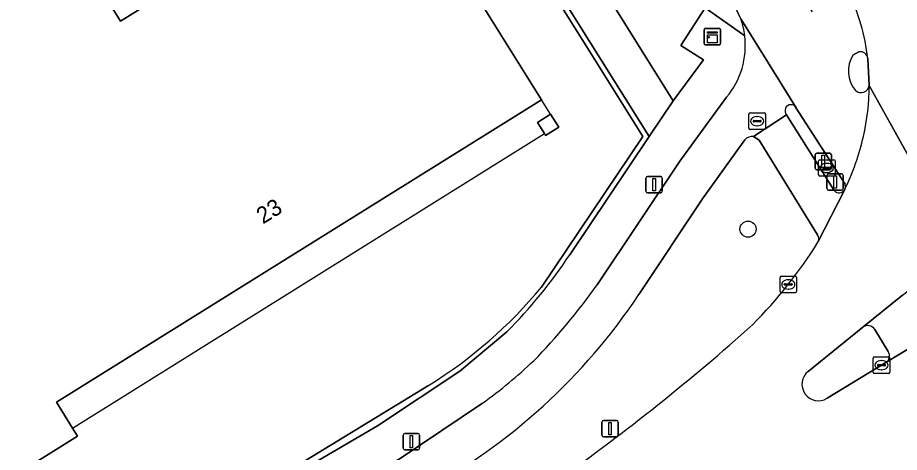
# Model space of a CAD drawing. Extents: x 156702 to 158052, y 387630 to 388992.
# Drawn here: x 157910.9 to 157964.3, y 388566 to 388592.3 of the extents above; entities that cross this region are included whole.
import ezdxf

# ---------------------------------------------------------------- set-up
doc = ezdxf.new("R2010")
doc.units = 0
for name, color, linetype in [('IMGEO_Berm_groen', 7, 'Continuous'), ('IMGEO_Boom', 7, 'Continuous'), ('IMGEO_Brandkraan', 7, 'Continuous'), ('IMGEO_Drukknoppaal', 7, 'Continuous'), ('IMGEO_Erf', 7, 'Continuous'), ('IMGEO_Fietspad_open', 7, 'Continuous'), ('IMGEO_Groenvoorziening', 7, 'Continuous'), ('IMGEO_Hek', 7, 'Continuous'), ('IMGEO_Kast', 7, 'Continuous'), ('IMGEO_Kolk', 7, 'Continuous'), ('IMGEO_Lichtmast', 7, 'Continuous'), ('IMGEO_Pand', 7, 'Continuous'), ('IMGEO_Pand_nummerreeks', 7, 'Continuous'), ('IMGEO_Pand_overbouw', 7, 'Continuous'), ('IMGEO_Rijbaan_lokaal_gesloten', 7, 'Continuous'), ('IMGEO_Rijbaan_regionaal_gesloten', 7, 'Continuous'), ('IMGEO_Rioolput', 7, 'Continuous'), ('IMGEO_Verkeerseiland_gesloten', 7, 'Continuous'), ('IMGEO_Verkeerseiland_open', 7, 'Continuous'), ('IMGEO_Verkeersregelinstallatiepaal', 7, 'Continuous'), ('IMGEO_Voetpad_open', 7, 'Continuous')]:
    doc.layers.add(name, color=color, linetype=linetype)

msp = doc.modelspace()

# ---------------------------------------------------------------- linework, layer by layer
at = {"layer": 'IMGEO_Berm_groen'}
for points in [[(157954.927, 388584.899), (157952.413, 388581.397), (157948.511, 388575.538)], [(157959.34, 388579.16), (157955.792, 388584.884), (157955.46, 388585.106)]]:
    msp.add_lwpolyline(points, dxfattribs=at)
for centre, radius, start, end in [((157955.356, 388584.584), 0.532, 78.7412, 143.7079), ((157958.922, 388578.915), 0.485, 334.4499, 30.3429), ((157934.754, 388594.145), 29.047, 315.3164, 327.8927), ((157918.015, 388595.904), 36.671, 298.3632, 326.264), ((157866.867, 388672.709), 132.809, 305.31667, 311.81023)]:
    msp.add_arc(centre, radius, start, end, dxfattribs=at)
at = {"layer": 'IMGEO_Boom'}
msp.add_circle((157955.124, 388579.503), 0.489, dxfattribs=at)
at = {"layer": 'IMGEO_Brandkraan'}
for p, q in [((157959.401, 388582.78), (157959.401, 388583.632)), ((157959.476, 388583.706), (157960.328, 388583.706)), ((157959.703, 388583.249), (157960.101, 388583.249)), ((157959.889, 388583.486), (157959.914, 388583.486)), ((157960.402, 388583.632), (157960.402, 388582.78)), ((157960.328, 388582.706), (157959.476, 388582.706)), ((157959.66, 388583.2), (157959.66, 388583.212)), ((157960.098, 388583.163), (157959.7, 388583.163)), ((157959.912, 388582.926), (157959.887, 388582.926)), ((157960.144, 388583.212), (157960.144, 388583.2))]:
    msp.add_line(p, q, dxfattribs=at)
for points in [[(157959.401, 388582.78), (157959.401, 388583.632)], [(157959.476, 388583.706), (157960.328, 388583.706)], [(157960.402, 388583.632), (157960.402, 388582.78)], [(157960.328, 388582.706), (157959.476, 388582.706)]]:
    msp.add_lwpolyline(points, dxfattribs=at)
for centre, radius, start, end in [((157959.478, 388583.63), 0.0765, 91.552, 178.448), ((157959.478, 388583.63), 0.0765, 91.552, 178.448), ((157959.7, 388583.209), 0.0403, 85.8775, 175.7526), ((157960.105, 388583.211), 0.0386, 1.7309, 96.639), ((157960.326, 388583.63), 0.0765, 1.552, 88.448), ((157960.326, 388583.63), 0.0765, 1.552, 88.448), ((157959.478, 388582.782), 0.0765, 181.552, 268.448), ((157959.478, 388582.782), 0.0765, 181.552, 268.448), ((157959.697, 388583.199), 0.0366, 178.938, 274.7102), ((157960.101, 388583.206), 0.043, 264.8664, 352.4533), ((157960.326, 388582.782), 0.0765, 271.552, 358.448), ((157960.326, 388582.782), 0.0765, 271.552, 358.448)]:
    msp.add_arc(centre, radius, start, end, dxfattribs=at)
for centre, major_axis, ratio, start_param, end_param in [((157959.888, 388583.206), (-0.387, 0.002), 0.722429, 4.712389, 7.853982), ((157959.913, 388583.206), (-0.39, 0.002), 0.717154, 1.570796, 4.712389)]:
    msp.add_ellipse(centre, major_axis=major_axis, ratio=ratio, start_param=start_param, end_param=end_param, dxfattribs=at)
at = {"layer": 'IMGEO_Drukknoppaal'}
for p, q in [((157959.183, 388583.196), (157959.183, 388583.996)), ((157959.183, 388583.996), (157959.183, 388583.196)), ((157959.283, 388584.096), (157960.073, 388584.096)), ((157960.073, 388584.096), (157959.283, 388584.096)), ((157960.173, 388583.996), (157960.173, 388583.196)), ((157960.173, 388583.196), (157960.173, 388583.996)), ((157960.073, 388583.096), (157959.283, 388583.096)), ((157959.283, 388583.096), (157960.073, 388583.096))]:
    msp.add_line(p, q, dxfattribs=at)
msp.add_lwpolyline([(157959.603, 388583.971), (157959.753, 388583.971), (157959.753, 388583.221), (157959.603, 388583.221), (157959.603, 388583.971)], dxfattribs=at)
for centre, start, end in [((157959.283, 388583.996), 90, 180), ((157959.283, 388583.996), 90, 180), ((157960.073, 388583.996), 0, 90), ((157960.073, 388583.996), 360, 90), ((157959.283, 388583.196), 180, 270), ((157959.283, 388583.196), 180, 270), ((157960.073, 388583.196), 270, 0), ((157960.073, 388583.196), 270, 0)]:
    msp.add_arc(centre, 0.1, start, end, dxfattribs=at)
at = {"layer": 'IMGEO_Erf'}
for points in [[(157948.757, 388585.103), (157945.61, 388590.115), (157919.697, 388631.383)], [(157863.84, 388596.769), (157846.071, 388585.831), (157845.161, 388585.276), (157845.206, 388585.216), (157845.979, 388584.198), (157852.72, 388575.415), (157852.82, 388575.493), (157856.311, 388570.878), (157873.067, 388548.722), (157876.307, 388544.438), (157879.966, 388539.6), (157881.966, 388538.145), (157884.382, 388537.75), (157886.516, 388538.265), (157912.593, 388554.443), (157921.94, 388561.605), (157926.695, 388564.507), (157935.759, 388570.044)], [(157942.609, 388575.997), (157948.757, 388585.103)]]:
    msp.add_lwpolyline(points, dxfattribs=at)
for points in [[(157913.225, 388569.027), (157914.19, 388567.452), (157914.494, 388566.97), (157908.34, 388563.13), (157908.075, 388563.555), (157891.158, 388552.943), (157865.87, 388592.617), (157883.193, 388603.423), (157883.007, 388603.739), (157889.176, 388607.593), (157889.39, 388607.278), (157898.345, 388612.873), (157902.499, 388615.468), (157917.093, 388592.095), (157924.551, 388596.738), (157933.319, 388602.195), (157942.615, 388587.321)], [(157942.786, 388585.292), (157942.362, 388585.956), (157943.147, 388586.459), (157943.658, 388585.673), (157942.858, 388585.18)]]:
    msp.add_lwpolyline(points, close=True, dxfattribs=at)
msp.add_arc((157921.347, 388593.545), 27.568, 301.5184, 320.4662, dxfattribs=at)
at = {"layer": 'IMGEO_Fietspad_open'}
for points in [[(157959.029, 388592.654), (157957.588, 388594.939), (157954.357, 388592.926), (157954.548, 388592.518), (157954.685, 388592.236), (157956.324, 388589.617), (157958.047, 388586.855), (157958.045, 388586.83), (157960.999, 388582.223)], [(157958.045, 388586.83), (157958.047, 388586.855), (157956.324, 388589.617), (157954.685, 388592.236)], [(157961.476, 388590.034), (157961.842, 388590.238)], [(157953.825, 388587.483), (157950.99, 388583.61), (157945.972, 388576.134)], [(157955.46, 388585.106), (157957.459, 388586.428)], [(157948.511, 388575.538), (157952.413, 388581.397), (157954.927, 388584.899)], [(157939.034, 388568.961), (157934.042, 388565.621), (157923.682, 388559.554)]]:
    msp.add_lwpolyline(points, dxfattribs=at)
for centre, radius, start, end in [((157949.872, 388588.389), 12.592, 6.6249, 25.8715), ((157950.055, 388590.624), 4.902, 6.9137, 19.1984), ((157950.053, 388590.619), 4.905, 320.2617, 6.9692), ((157961.907, 388589.762), 0.48, 9.569, 97.7205), ((157962.998, 388589.073), 1.8, 147.74, 220.6754), ((157961.97, 388588.275), 0.504, 228.0298, 351.3299), ((157948.084, 388588.291), 14.386, 347.2395, 359.6319), ((157957.72, 388586.676), 0.36, 25.2943, 223.6064), ((157955.356, 388584.584), 0.532, 78.7412, 143.7079), ((157947.944, 388588.313), 14.527, 333.8086, 347.2797), ((157960.586, 388582.087), 0.434, 334.6452, 18.2464), ((157915.537, 388597.592), 37.239, 315.5843, 324.8144), ((157918.015, 388595.904), 36.671, 298.3632, 326.264), ((157921.547, 388593.233), 29.915, 305.7707, 313.4907)]:
    msp.add_arc(centre, radius, start, end, dxfattribs=at)
at = {"layer": 'IMGEO_Groenvoorziening'}
for points in [[(157954.685, 388592.236), (157954.548, 388592.518), (157954.357, 388592.926), (157954.322, 388592.982), (157844.53, 388769.241)], [(157880.239, 388699.921), (157928.508, 388622.637), (157945.606, 388595.262), (157950.595, 388587.277), (157952.433, 388589.75), (157951.047, 388590.629), (157952.528, 388592.898), (157954.922, 388591.214)], [(157944.325, 388577.946), (157949.123, 388585.105), (157943.354, 388594.324), (157926.051, 388621.896), (157924.743, 388623.999), (157911.853, 388644.72), (157899.219, 388665.03), (157885.512, 388656.483), (157868.846, 388646.09), (157821.438, 388616.579), (157821.49, 388616.464), (157825.955, 388610.584), (157827.357, 388611.329), (157826.47, 388612.778), (157823.972, 388616.855), (157851.434, 388634.015), (157854.036, 388629.957), (157854.857, 388628.676), (157863.382, 388633.842), (157862.483, 388635.263), (157859.899, 388639.35)], [(157859.899, 388639.35), (157891.839, 388659.234), (157894.466, 388655.043), (157898.194, 388657.38), (157908.656, 388640.687), (157904.927, 388638.35), (157911.548, 388627.786), (157906.588, 388624.86), (157907.31, 388623.673), (157919.697, 388631.383), (157945.61, 388590.115), (157948.757, 388585.103), (157942.609, 388575.997)], [(157935.759, 388570.044), (157926.695, 388564.507), (157921.94, 388561.605), (157912.593, 388554.443), (157886.516, 388538.265), (157884.382, 388537.75), (157881.966, 388538.145), (157879.966, 388539.6), (157876.307, 388544.438), (157876.167, 388544.326), (157879.78, 388539.386), (157881.963, 388537.803), (157884.345, 388537.434), (157886.442, 388537.927), (157914.286, 388554.915), (157915.878, 388556.27), (157918.49, 388558.725), (157922.488, 388561.637), (157932.675, 388567.591), (157937.655, 388570.903), (157940.514, 388573.276)]]:
    msp.add_lwpolyline(points, dxfattribs=at)
for centre, radius, start, end in [((157950.055, 388590.624), 4.902, 6.9137, 19.1984), ((157917.286, 388596.121), 32.579, 315.4756, 326.0914), ((157921.347, 388593.545), 27.568, 301.5184, 320.4662)]:
    msp.add_arc(centre, radius, start, end, dxfattribs=at)
at = {"layer": 'IMGEO_Hek'}
for points in [[(157907.31, 388623.673), (157919.697, 388631.383), (157945.61, 388590.115)], [(157945.61, 388590.115), (157948.757, 388585.103), (157942.609, 388575.997)], [(157935.759, 388570.044), (157926.695, 388564.507)]]:
    msp.add_lwpolyline(points, dxfattribs=at)
msp.add_arc((157921.347, 388593.545), 27.568, 301.5184, 320.4662, dxfattribs=at)
at = {"layer": 'IMGEO_Kast'}
for p, q in [((157952.462, 388590.731), (157952.462, 388591.572)), ((157952.462, 388591.572), (157952.462, 388590.731)), ((157952.537, 388591.656), (157953.378, 388591.656)), ((157953.378, 388591.656), (157952.537, 388591.656)), ((157953.462, 388591.581), (157953.462, 388590.74)), ((157953.462, 388590.74), (157953.462, 388591.581)), ((157953.387, 388590.656), (157952.546, 388590.656)), ((157952.546, 388590.656), (157953.387, 388590.656))]:
    msp.add_line(p, q, dxfattribs=at)
for points in [[(157952.657, 388591.446), (157953.257, 388591.446), (157953.257, 388591.361), (157952.657, 388591.361), (157952.657, 388591.446)], [(157952.657, 388591.271), (157953.257, 388591.271), (157953.257, 388590.782), (157952.657, 388590.782), (157952.657, 388591.271)]]:
    msp.add_lwpolyline(points, dxfattribs=at)
msp.add_circle((157952.741, 388591.12), 0.0377, dxfattribs=at)
for centre, start, end in [((157952.54, 388591.578), 92.4484, 184.2845), ((157952.54, 388591.578), 92.4484, 184.2845), ((157953.384, 388591.578), 2.4484, 94.2845), ((157953.384, 388591.578), 2.4484, 94.2845), ((157952.54, 388590.734), 182.4484, 274.2845), ((157952.54, 388590.734), 182.4484, 274.2845), ((157953.384, 388590.734), 272.4484, 4.2845), ((157953.384, 388590.734), 272.4484, 4.2845)]:
    msp.add_arc(centre, 0.0779, start, end, dxfattribs=at)
at = {"layer": 'IMGEO_Kolk'}
for p, q in [((157955.173, 388585.614), (157955.173, 388586.466)), ((157955.248, 388586.54), (157956.1, 388586.54)), ((157956.174, 388586.466), (157956.174, 388585.614)), ((157955.432, 388586.034), (157955.432, 388586.046)), ((157955.87, 388585.997), (157955.472, 388585.997)), ((157955.475, 388586.083), (157955.873, 388586.083)), ((157955.661, 388586.32), (157955.686, 388586.32)), ((157955.916, 388586.046), (157955.916, 388586.034)), ((157956.1, 388585.54), (157955.248, 388585.54)), ((157955.684, 388585.76), (157955.659, 388585.76)), ((157957.062, 388575.729), (157957.062, 388576.581)), ((157957.137, 388576.655), (157957.989, 388576.655)), ((157957.55, 388576.435), (157957.575, 388576.435)), ((157958.063, 388576.581), (157958.063, 388575.729)), ((157957.321, 388576.149), (157957.321, 388576.161)), ((157957.759, 388576.112), (157957.361, 388576.112)), ((157957.364, 388576.198), (157957.762, 388576.198)), ((157957.573, 388575.875), (157957.548, 388575.875)), ((157957.805, 388576.161), (157957.805, 388576.149)), ((157957.989, 388575.655), (157957.137, 388575.655))]:
    msp.add_line(p, q, dxfattribs=at)
for points in [[(157955.173, 388585.614), (157955.173, 388586.466)], [(157955.248, 388586.54), (157956.1, 388586.54)], [(157956.174, 388586.466), (157956.174, 388585.614)], [(157956.1, 388585.54), (157955.248, 388585.54)], [(157957.062, 388575.729), (157957.062, 388576.581)], [(157957.137, 388576.655), (157957.989, 388576.655)], [(157958.063, 388576.581), (157958.063, 388575.729)], [(157957.989, 388575.655), (157957.137, 388575.655)]]:
    msp.add_lwpolyline(points, dxfattribs=at)
for centre, radius, start, end in [((157955.25, 388586.464), 0.0765, 91.552, 178.448), ((157955.25, 388586.464), 0.0765, 91.552, 178.448), ((157956.098, 388586.464), 0.0765, 1.552, 88.448), ((157956.098, 388586.464), 0.0765, 1.552, 88.448), ((157955.472, 388586.043), 0.0403, 85.8775, 175.7526), ((157955.469, 388586.033), 0.0366, 178.938, 274.7102), ((157955.873, 388586.04), 0.043, 264.8664, 352.4533), ((157955.877, 388586.045), 0.0386, 1.7309, 96.639), ((157955.25, 388585.616), 0.0765, 181.552, 268.448), ((157955.25, 388585.616), 0.0765, 181.552, 268.448), ((157956.098, 388585.616), 0.0765, 271.552, 358.448), ((157956.098, 388585.616), 0.0765, 271.552, 358.448), ((157957.139, 388576.579), 0.0765, 91.552, 178.448), ((157957.139, 388576.579), 0.0765, 91.552, 178.448), ((157957.987, 388576.579), 0.0765, 1.552, 88.448), ((157957.987, 388576.579), 0.0765, 1.552, 88.448), ((157957.361, 388576.158), 0.0403, 85.8775, 175.7526), ((157957.358, 388576.148), 0.0366, 178.938, 274.7102), ((157957.762, 388576.155), 0.043, 264.8664, 352.4533), ((157957.766, 388576.16), 0.0386, 1.7309, 96.639), ((157957.139, 388575.731), 0.0765, 181.552, 268.448), ((157957.139, 388575.731), 0.0765, 181.552, 268.448), ((157957.987, 388575.731), 0.0765, 271.552, 358.448), ((157957.987, 388575.731), 0.0765, 271.552, 358.448)]:
    msp.add_arc(centre, radius, start, end, dxfattribs=at)
for centre, major_axis, ratio, start_param, end_param in [((157955.66, 388586.04), (-0.387, 0.002), 0.722429, 4.712389, 7.853982), ((157955.685, 388586.04), (-0.39, 0.002), 0.717154, 1.570796, 4.712389), ((157957.549, 388576.155), (-0.387, 0.002), 0.722429, 4.712389, 7.853982), ((157957.574, 388576.155), (-0.39, 0.002), 0.717154, 1.570796, 4.712389)]:
    msp.add_ellipse(centre, major_axis=major_axis, ratio=ratio, start_param=start_param, end_param=end_param, dxfattribs=at)
at = {"layer": 'IMGEO_Lichtmast'}
for p, q in [((157949.039, 388582.697), (157949.829, 388582.697)), ((157949.829, 388582.697), (157949.039, 388582.697)), ((157948.939, 388581.797), (157948.939, 388582.597)), ((157948.939, 388582.597), (157948.939, 388581.797)), ((157949.929, 388582.597), (157949.929, 388581.797)), ((157949.929, 388581.797), (157949.929, 388582.597)), ((157949.829, 388581.697), (157949.039, 388581.697)), ((157949.039, 388581.697), (157949.829, 388581.697)), ((157946.268, 388567.025), (157946.268, 388567.825)), ((157946.268, 388567.825), (157946.268, 388567.025)), ((157946.368, 388567.925), (157947.158, 388567.925)), ((157947.158, 388567.925), (157946.368, 388567.925)), ((157947.258, 388567.825), (157947.258, 388567.025)), ((157947.258, 388567.025), (157947.258, 388567.825)), ((157934.231, 388566.235), (157934.231, 388567.035)), ((157934.231, 388567.035), (157934.231, 388566.235)), ((157934.331, 388567.135), (157935.121, 388567.135)), ((157935.121, 388567.135), (157934.331, 388567.135)), ((157935.221, 388567.035), (157935.221, 388566.235)), ((157935.221, 388566.235), (157935.221, 388567.035)), ((157947.158, 388566.925), (157946.368, 388566.925)), ((157946.368, 388566.925), (157947.158, 388566.925)), ((157935.121, 388566.135), (157934.331, 388566.135)), ((157934.331, 388566.135), (157935.121, 388566.135))]:
    msp.add_line(p, q, dxfattribs=at)
for points in [[(157949.359, 388582.572), (157949.509, 388582.572), (157949.509, 388581.822), (157949.359, 388581.822), (157949.359, 388582.572)], [(157946.688, 388567.8), (157946.838, 388567.8), (157946.838, 388567.05), (157946.688, 388567.05), (157946.688, 388567.8)], [(157934.651, 388567.01), (157934.801, 388567.01), (157934.801, 388566.26), (157934.651, 388566.26), (157934.651, 388567.01)]]:
    msp.add_lwpolyline(points, dxfattribs=at)
for centre, start, end in [((157949.039, 388582.597), 90, 180), ((157949.039, 388582.597), 90, 180), ((157949.829, 388582.597), 0, 90), ((157949.829, 388582.597), 360, 90), ((157949.039, 388581.797), 180, 270), ((157949.039, 388581.797), 180, 270), ((157949.829, 388581.797), 270, 0), ((157949.829, 388581.797), 270, 0), ((157946.368, 388567.825), 90, 180), ((157946.368, 388567.825), 90, 180), ((157947.158, 388567.825), 0, 90), ((157947.158, 388567.825), 360, 90), ((157934.331, 388567.035), 90, 180), ((157934.331, 388567.035), 90, 180), ((157935.121, 388567.035), 0, 90), ((157935.121, 388567.035), 360, 90), ((157946.368, 388567.025), 180, 270), ((157946.368, 388567.025), 180, 270), ((157947.158, 388567.025), 270, 0), ((157947.158, 388567.025), 270, 0), ((157934.331, 388566.235), 180, 270), ((157934.331, 388566.235), 180, 270), ((157935.121, 388566.235), 270, 0), ((157935.121, 388566.235), 270, 0)]:
    msp.add_arc(centre, 0.1, start, end, dxfattribs=at)
at = {"layer": 'IMGEO_Pand'}
for points in [[(157914.19, 388567.452), (157913.225, 388569.027), (157942.615, 388587.321), (157933.319, 388602.195), (157924.551, 388596.738), (157917.093, 388592.095), (157902.499, 388615.468), (157898.345, 388612.873), (157889.39, 388607.278), (157889.176, 388607.593), (157883.007, 388603.739), (157883.193, 388603.423), (157865.87, 388592.617), (157891.158, 388552.943), (157908.075, 388563.555), (157908.34, 388563.13), (157914.494, 388566.97)], [(157942.858, 388585.18), (157943.658, 388585.673), (157943.147, 388586.459), (157942.362, 388585.956), (157942.786, 388585.292)]]:
    msp.add_lwpolyline(points, close=True, dxfattribs=at)
at = {"layer": 'IMGEO_Pand_overbouw'}
msp.add_lwpolyline([(157943.658, 388585.673), (157943.147, 388586.459), (157942.615, 388587.321), (157913.225, 388569.027), (157914.19, 388567.452), (157942.786, 388585.292), (157942.858, 388585.18)], close=True, dxfattribs=at)
at = {"layer": 'IMGEO_Rijbaan_lokaal_gesloten'}
for points in [[(157958.762, 388570.89), (157962.072, 388573.558), (157964.476, 388575.497), (157964.547, 388575.554), (157967.86, 388578.249), (157967.966, 388578.311), (157962.469, 388588.199)], [(157960.979, 388581.901), (157959.359, 388578.706)], [(157975.665, 388567.04), (157969.867, 388575.31), (157969.735, 388575.217), (157966.125, 388573.037), (157966.08, 388573.009), (157963.461, 388571.418), (157959.907, 388569.259)]]:
    msp.add_lwpolyline(points, dxfattribs=at)
for centre, radius, start, end in [((157948.084, 388588.291), 14.386, 347.2395, 359.6319), ((157947.944, 388588.313), 14.527, 333.8086, 347.2797), ((157934.754, 388594.145), 29.047, 315.3164, 327.8927), ((157866.867, 388672.709), 132.809, 305.31667, 311.81023), ((157959.389, 388570.113), 0.999, 128.9098, 301.2297)]:
    msp.add_arc(centre, radius, start, end, dxfattribs=at)
at = {"layer": 'IMGEO_Rijbaan_regionaal_gesloten'}
msp.add_lwpolyline([(157962.38, 388589.842), (157962.469, 388588.199), (157967.966, 388578.311), (157968.829, 388579.007)], dxfattribs=at)
msp.add_arc((157949.872, 388588.389), 12.592, 6.6249, 25.8715, dxfattribs=at)
at = {"layer": 'IMGEO_Rioolput'}
for p, q in [((157962.705, 388570.841), (157962.705, 388571.693)), ((157962.78, 388571.767), (157963.632, 388571.767)), ((157963.193, 388571.547), (157963.218, 388571.547)), ((157963.706, 388571.693), (157963.706, 388570.841)), ((157962.964, 388571.261), (157962.964, 388571.273)), ((157963.402, 388571.224), (157963.004, 388571.224)), ((157963.007, 388571.31), (157963.405, 388571.31)), ((157963.216, 388570.987), (157963.191, 388570.987)), ((157963.448, 388571.273), (157963.448, 388571.261)), ((157963.632, 388570.767), (157962.78, 388570.767))]:
    msp.add_line(p, q, dxfattribs=at)
for points in [[(157962.705, 388570.841), (157962.705, 388571.693)], [(157962.78, 388571.767), (157963.632, 388571.767)], [(157963.706, 388571.693), (157963.706, 388570.841)], [(157963.632, 388570.767), (157962.78, 388570.767)]]:
    msp.add_lwpolyline(points, dxfattribs=at)
for centre, radius, start, end in [((157962.782, 388571.691), 0.0765, 91.552, 178.448), ((157962.782, 388571.691), 0.0765, 91.552, 178.448), ((157963.63, 388571.691), 0.0765, 1.552, 88.448), ((157963.63, 388571.691), 0.0765, 1.552, 88.448), ((157963.004, 388571.27), 0.0403, 85.8775, 175.7526), ((157963.001, 388571.26), 0.0366, 178.938, 274.7102), ((157963.405, 388571.267), 0.043, 264.8664, 352.4533), ((157963.409, 388571.272), 0.0386, 1.7309, 96.639), ((157962.782, 388570.843), 0.0765, 181.552, 268.448), ((157962.782, 388570.843), 0.0765, 181.552, 268.448), ((157963.63, 388570.843), 0.0765, 271.552, 358.448), ((157963.63, 388570.843), 0.0765, 271.552, 358.448)]:
    msp.add_arc(centre, radius, start, end, dxfattribs=at)
for centre, major_axis, ratio, start_param, end_param in [((157963.192, 388571.267), (-0.387, 0.002), 0.722429, 4.712389, 7.853982), ((157963.217, 388571.267), (-0.39, 0.002), 0.717154, 1.570796, 4.712389)]:
    msp.add_ellipse(centre, major_axis=major_axis, ratio=ratio, start_param=start_param, end_param=end_param, dxfattribs=at)
at = {"layer": 'IMGEO_Verkeerseiland_gesloten'}
for points in [[(157957.459, 388586.428), (157960.346, 388581.832)], [(157960.999, 388582.223), (157958.045, 388586.83)]]:
    msp.add_lwpolyline(points, dxfattribs=at)
for centre, radius, start, end in [((157957.72, 388586.676), 0.36, 25.2943, 223.6064), ((157960.586, 388582.087), 0.434, 334.6452, 18.2464), ((157960.639, 388582.084), 0.386, 220.7155, 331.7264)]:
    msp.add_arc(centre, radius, start, end, dxfattribs=at)
at = {"layer": 'IMGEO_Verkeerseiland_open'}
for points in [[(157961.842, 388590.238), (157961.476, 388590.034)], [(157962.469, 388588.199), (157962.38, 388589.842)], [(157962.072, 388573.558), (157958.762, 388570.89)], [(157963.618, 388572.103), (157962.803, 388573.425)], [(157959.907, 388569.259), (157963.461, 388571.418)]]:
    msp.add_lwpolyline(points, dxfattribs=at)
for centre, radius, start, end in [((157961.907, 388589.762), 0.48, 9.569, 97.7205), ((157962.998, 388589.073), 1.8, 147.74, 220.6754), ((157961.97, 388588.275), 0.504, 228.0298, 351.3299), ((157962.378, 388573.162), 0.5, 31.722, 127.6545), ((157963.193, 388571.84), 0.5, 302.4158, 31.7661), ((157959.389, 388570.113), 0.999, 128.9098, 301.2297)]:
    msp.add_arc(centre, radius, start, end, dxfattribs=at)
at = {"layer": 'IMGEO_Verkeersregelinstallatiepaal'}
for p, q in [((157959.903, 388581.956), (157959.903, 388582.756)), ((157959.903, 388582.756), (157959.903, 388581.956)), ((157960.003, 388582.856), (157960.793, 388582.856)), ((157960.793, 388582.856), (157960.003, 388582.856)), ((157960.893, 388582.756), (157960.893, 388581.956)), ((157960.893, 388581.956), (157960.893, 388582.756)), ((157960.793, 388581.856), (157960.003, 388581.856)), ((157960.003, 388581.856), (157960.793, 388581.856))]:
    msp.add_line(p, q, dxfattribs=at)
msp.add_lwpolyline([(157960.323, 388582.731), (157960.473, 388582.731), (157960.473, 388581.981), (157960.323, 388581.981), (157960.323, 388582.731)], dxfattribs=at)
for centre, start, end in [((157960.003, 388582.756), 90, 180), ((157960.003, 388582.756), 90, 180), ((157960.793, 388582.756), 0, 90), ((157960.793, 388582.756), 360, 90), ((157960.003, 388581.956), 180, 270), ((157960.003, 388581.956), 180, 270), ((157960.793, 388581.956), 270, 0), ((157960.793, 388581.956), 270, 0)]:
    msp.add_arc(centre, 0.1, start, end, dxfattribs=at)
at = {"layer": 'IMGEO_Voetpad_open'}
msp.add_lwpolyline([(157880.239, 388699.921), (157874.791, 388708.644), (157851.316, 388746.23), (157849.268, 388744.926), (157852.086, 388740.586), (157856.05, 388734.198), (157867.882, 388715.132), (157872.247, 388708.041), (157883.728, 388689.908), (157884.611, 388688.513), (157899.219, 388665.03), (157911.853, 388644.72), (157924.743, 388623.999), (157926.051, 388621.896), (157943.354, 388594.324), (157949.123, 388585.105), (157950.595, 388587.277), (157945.606, 388595.262), (157928.508, 388622.637)], close=True, dxfattribs=at)
for points in [[(157954.922, 388591.214), (157952.528, 388592.898), (157951.047, 388590.629), (157952.433, 388589.75), (157950.595, 388587.277), (157949.123, 388585.105), (157944.325, 388577.946)], [(157945.972, 388576.134), (157950.99, 388583.61), (157953.825, 388587.483)], [(157960.346, 388581.832), (157957.459, 388586.428), (157955.46, 388585.106), (157955.792, 388584.884), (157959.34, 388579.16)], [(157959.359, 388578.706), (157960.979, 388581.901)], [(157964.476, 388575.497), (157962.072, 388573.558)], [(157940.514, 388573.276), (157937.655, 388570.903), (157932.675, 388567.591), (157922.488, 388561.637), (157918.49, 388558.725), (157915.878, 388556.27), (157914.286, 388554.915), (157886.442, 388537.927), (157882.423, 388535.475)], [(157962.803, 388573.425), (157963.618, 388572.103)], [(157963.461, 388571.418), (157966.08, 388573.009)], [(157923.682, 388559.554), (157934.042, 388565.621), (157939.034, 388568.961)]]:
    msp.add_lwpolyline(points, dxfattribs=at)
for centre, radius, start, end in [((157950.053, 388590.619), 4.905, 320.2617, 6.9692), ((157960.639, 388582.084), 0.386, 220.7155, 331.7264), ((157958.922, 388578.915), 0.485, 334.4499, 30.3429), ((157917.286, 388596.121), 32.579, 315.4756, 326.0914), ((157915.537, 388597.592), 37.239, 315.5843, 324.8144), ((157962.378, 388573.162), 0.5, 31.722, 127.6545), ((157963.193, 388571.84), 0.5, 302.4158, 31.7661), ((157921.547, 388593.233), 29.915, 305.7707, 313.4907)]:
    msp.add_arc(centre, radius, start, end, dxfattribs=at)

# ---------------------------------------------------------------- texts
at = {"layer": 'IMGEO_Pand_nummerreeks'}
msp.add_text('23', height=1, rotation=31.9001, dxfattribs=at).set_placement((157925.732, 388579.78))

doc.saveas('drawing.dxf')
